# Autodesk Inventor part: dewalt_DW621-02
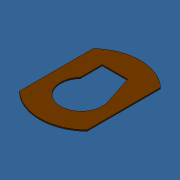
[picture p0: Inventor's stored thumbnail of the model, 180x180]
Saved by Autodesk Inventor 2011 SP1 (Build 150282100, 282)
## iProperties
Created: 2011-02
Part Number: dewalt_DW621-02
Material: Polyaryletherketon-Kunststoff
Catalog Web Link: www.mittelmeyer.de
Document SubType Name: Modellieren
Designer: TMT
Manufacturer: Standard
Standards Organization: Custom
Density: 1.32 g/cm^3
Author: TMT
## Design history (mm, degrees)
sketch "Skizze2"
  geometry: L1 (-55, 82)-(55, 82); L2 (55, 82)-(55, -82); L3 (55, -82)-(-55, -82); L4 (-55, -82)-(-55, 82); L5 (0, -114.8)-(0, 114.8) reference; L6 (-77, 0)-(77, 0) reference
  constraints: 8 end point, 2 parallel, 1 horizontal, 1 perpendicular, 2 other
  dimensions: "d4" = 164 distance of L3.end L1.start (= laenge_01); "d5" = 110 distance of L2.end L3.end (= breite_01)
extrude "Extrusion2" new body sketch "Skizze2" distance "d6" = 2 (= hoehe_01); taper "d7" = 0 deg
sketch "Skizze3"
  geometry: L1 (55, 82)-(55, -82) reference; L2 (-55, 82)-(55, 82) reference; L3 (-55, -82)-(-55, 82) reference; L4 (55, -82)-(-55, -82) reference; L5 (-111.65, 0)-(111.65, 0) reference; L6 (0, -114.8)-(0, 114.8) reference; L7 (-55, -60)-(-55, -82); L8 (-55, -82)-(55, -82); L9 (55, -82)-(55, -60); A1 r 79.75 centre (0, -2.25) between (55, -60) and (-55, -60); 1 further point
  constraints: 6 end point, 3 point on line, 2 collinear, 2 point on circle, 1 centre point, 1 perpendicular, 1 tangent
  dimensions: "d8" = 60 distance from line of L9.end L5
extrude "Extrusion3" cut sketch "Skizze3" stored distance "d9" = 21.5; taper "d10" = 0 deg
sketch "Skizze4"
  geometry: L1 (0, -114.8)-(0, 114.8) reference; L2 (-77, 0)-(77, 0) reference; C1 r 34 at (0, -14); A1 r 79.75 centre (0, -2.25) between (-55, -60) and (55, -60) reference; 2 further points
  constraints: 2 point on line, 1 centre point, 1 point on circle
  dimensions: "d11" = 68 distance of C1.centre point (0, -82); "d12" = 68 diameter of C1
extrude "Extrusion4" cut sketch "Skizze4" stored distance "d13" = 27; taper "d14" = 0 deg
mirror "Spiegeln1"
sketch "Skizze21"
  geometry: L1 (-55, -60)-(-55, 60) reference; L2 (55, 60)-(55, -60) reference; L3 (-77, 0)-(77, 0) reference; L4 (0, -114.8)-(0, 114.8) reference; L5 (32.336, -3.493)-(16.579, 45); L6 (16.579, 45)-(-25, 45); L7 (-25, 45)-(-25, 9.043); A1 r 34 centre (0, -14) between (32.336, -3.493) and (-25, 9.043) reference; A2 r 79.75 centre (0, 2.25) between (55, 60) and (-55, 60) reference; 1 further point
  constraints: 6 end point, 2 parallel, 2 point on circle, 1 tangent
  dimensions: "d94" = 18 deg angle of L5 L2; "d95" = 30 distance between parallel lines of L7 L1; "d96" = 37 distance edge to line of A2 L6
extrude "Extrusion18" cut sketch "Skizze21" stored distance "d97" = 50; taper "d98" = 0 deg
node "Volumenkörper1"
node "Volumenkörpern"
node "Oberflächenkörpern"
other parameters: "laenge_01" = 164 [user parameter; used in 1 equation term], "breite_01" = 110 [user parameter; used in 1 equation term], "hoehe_01" = 2 [user parameter; used in 1 equation term]
